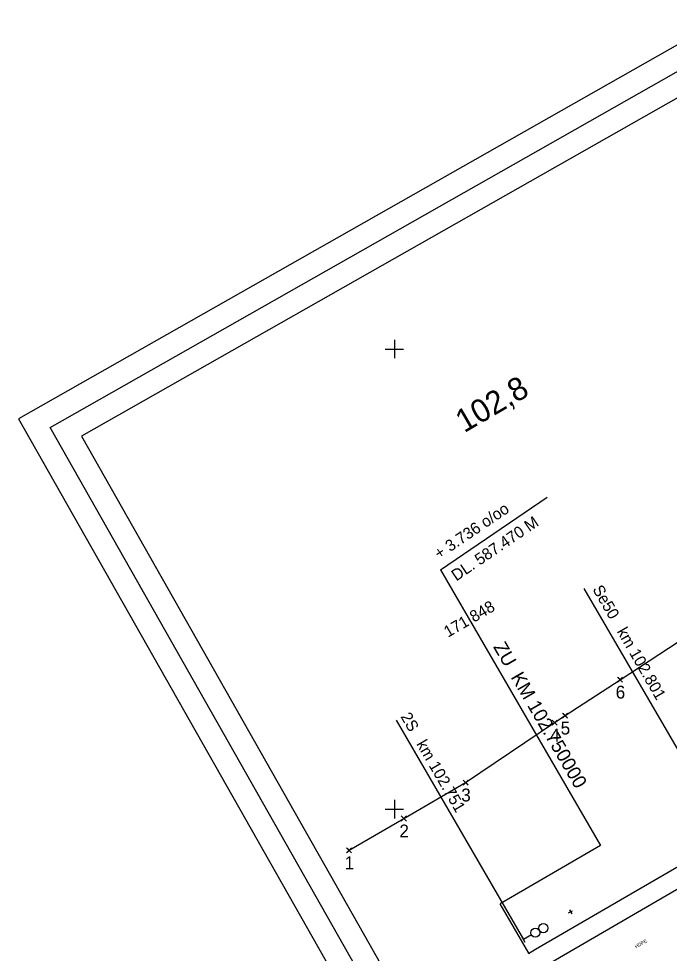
# Model space of a CAD drawing. Extents: x -566182 to -565305, y -1203073 to -1202401.
# Drawn here: x -566181.7 to -566040.2, y -1202931.3 to -1202728.2 of the extents above; entities that cross this region are included whole.
import ezdxf

# ---------------------------------------------------------------- set-up
doc = ezdxf.new("R2010")
doc.units = 0
for name, color, linetype in [('SZDC', 7, 'Continuous'), ('Vrstva 1', 7, 'Continuous'), ('Vrstva 12', 7, 'Continuous'), ('Vrstva 24', 7, 'Continuous'), ('Vrstva 25', 7, 'Continuous'), ('Vrstva 39', 7, 'Continuous'), ('Vrstva 42', 7, 'Continuous'), ('Vrstva 5', 7, 'Continuous'), ('Vrstva 6', 7, 'Continuous'), ('Vrstva 60', 7, 'Continuous'), ('Vrstva 7', 7, 'Continuous')]:
    doc.layers.add(name, color=color, linetype=linetype)

# ---------------------------------------------------------------- blocks, each defined once
blk = doc.blocks.new('C691')
at = {"layer": 'Vrstva 12'}
for p, q in [((-5, 0), (5, 0)), ((0, 5), (0, -5))]:
    blk.add_line(p, q, dxfattribs=at)
blk = doc.blocks.new('C569')
at = {"layer": 'Vrstva 24'}
for p, q in [((0, -7.5), (0, 7.5)), ((20, 0), (0, 0))]:
    blk.add_line(p, q, dxfattribs=at)
for centre in [(30, 0), (50, 0)]:
    blk.add_circle(centre, 10, dxfattribs=at)

msp = doc.modelspace()

# ---------------------------------------------------------------- linework, layer by layer
at = {"layer": 'SZDC'}
msp.add_lwpolyline([(-566109.86, -1202908.94), (-566097.96, -1202902.03), (-566084.51, -1202894.21), (-566065.16, -1202881.19), (-566062.89, -1202879.66), (-566050.93, -1202871.86), (-566034.12, -1202860.89), (-566014.69, -1202848.22), (-565999.33, -1202838.2), (-565981.56, -1202826.61), (-565964.56, -1202815.52), (-565946.25, -1202803.07), (-565943.74, -1202801.57), (-565935.57, -1202796.69), (-565927.13, -1202791.65), (-565924.54, -1202790.1), (-565905.03, -1202778.89), (-565894.6, -1202771.96), (-565883.49, -1202764.57), (-565860.68, -1202749.5), (-565834.73, -1202732.72)], dxfattribs=at)
at = {"layer": 'Vrstva 1'}
for points in [[(-566035.16, -1203073.47), (-565304.55, -1202658.99), (-565451.1, -1202400.68), (-566181.71, -1202815.16)], [(-565311.37, -1202657.11), (-566033.28, -1203066.66), (-566174.89, -1202817.04), (-565452.98, -1202407.49)], [(-566031.4, -1203059.85), (-565496.48, -1202756.39), (-565633.16, -1202515.46), (-566168.08, -1202818.92)]]:
    msp.add_lwpolyline(points, close=True, dxfattribs=at)
at = {"layer": 'Vrstva 5'}
for p, q in [((-566100, -1202798), (-566100, -1202802)), ((-566102, -1202800), (-566098, -1202800)), ((-566100, -1202898), (-566100, -1202902)), ((-566102, -1202900), (-566098, -1202900))]:
    msp.add_line(p, q, dxfattribs=at)
at = {"layer": 'Vrstva 6'}
for points in [[(-566068.74, -1202934.92), (-566067.2, -1202934.01), (-566009.26, -1202900.35), (-565952.55, -1202867.42), (-565900.78, -1202837.32), (-565844.77, -1202804.78), (-565792.03, -1202774.14)], [(-565967.23, -1202871.18), (-566010.28, -1202896.21), (-566069.32, -1202930.5), (-566070.86, -1202931.4)]]:
    msp.add_lwpolyline(points, dxfattribs=at)
at = {"layer": 'Vrstva 60'}
for p, q in [((-566090.01, -1202847.96), (-566066.79, -1202832.23)), ((-566090.01, -1202847.96), (-566055.2, -1202907.89)), ((-566058.78, -1202852.05), (-566029.01, -1202903.3)), ((-566050.48, -1202872.31), (-566051.48, -1202871.31)), ((-566050.48, -1202871.41), (-566051.48, -1202872.41)), ((-566051.38, -1202872.31), (-566050.38, -1202871.31)), ((-566051.38, -1202871.41), (-566050.38, -1202872.41)), ((-566050.93, -1202871.86), (-566050.93, -1202871.86)), ((-566062.44, -1202880.11), (-566063.44, -1202879.11)), ((-566062.44, -1202879.21), (-566063.44, -1202880.21)), ((-566063.34, -1202880.11), (-566062.34, -1202879.11)), ((-566063.34, -1202879.21), (-566062.34, -1202880.21)), ((-566099.63, -1202880.68), (-566071.96, -1202928.32)), ((-566064.71, -1202881.64), (-566065.71, -1202880.64)), ((-566064.71, -1202880.74), (-566065.71, -1202881.74)), ((-566065.61, -1202881.64), (-566064.61, -1202880.64)), ((-566065.61, -1202880.74), (-566064.61, -1202881.74)), ((-566065.16, -1202881.19), (-566065.16, -1202881.19)), ((-566062.89, -1202879.66), (-566062.89, -1202879.66)), ((-566084.06, -1202894.66), (-566085.06, -1202893.66)), ((-566084.06, -1202893.76), (-566085.06, -1202894.76)), ((-566084.96, -1202894.66), (-566083.96, -1202893.66)), ((-566084.96, -1202893.76), (-566083.96, -1202894.76)), ((-566084.51, -1202894.21), (-566084.51, -1202894.21)), ((-566097.51, -1202902.48), (-566098.51, -1202901.48)), ((-566097.51, -1202901.58), (-566098.51, -1202902.58)), ((-566098.41, -1202902.48), (-566097.41, -1202901.48)), ((-566098.41, -1202901.58), (-566097.41, -1202902.58)), ((-566097.96, -1202902.03), (-566097.96, -1202902.03)), ((-566055.2, -1202907.89), (-566077, -1202920.55)), ((-566109.41, -1202909.39), (-566110.41, -1202908.39)), ((-566109.41, -1202908.49), (-566110.41, -1202909.49)), ((-566110.31, -1202909.39), (-566109.31, -1202908.39)), ((-566110.31, -1202908.49), (-566109.31, -1202909.49)), ((-566109.86, -1202908.94), (-566109.86, -1202908.94)), ((-566070.75, -1202931.32), (-566077, -1202920.55))]:
    msp.add_line(p, q, dxfattribs=at)

# ---------------------------------------------------------------- block references
at = {"layer": 'Vrstva 12', "xscale": 0.09999990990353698, "yscale": 0.09999990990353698, "rotation": 30.000029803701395}
msp.add_blockref('C691', (-566061.7, -1202922.31), dxfattribs=at)
at = {"layer": 'Vrstva 24', "xscale": 0.10000006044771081, "yscale": 0.10000006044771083, "rotation": 29.642325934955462}
msp.add_blockref('C569', (-566071.96, -1202928.32), dxfattribs=at)

# ---------------------------------------------------------------- texts
at = {"layer": 'Vrstva 25'}
for s, p in [('Se50   km 102.801', (-566057.01, -1202852.19)), ('2S   km 102.751', (-566098.74, -1202879.86))]:
    msp.add_text(s, height=2.5, rotation=299.9873, dxfattribs=at).set_placement(p)
at = {"layer": 'Vrstva 39'}
for s, height, rotation, p in [('+ 3.736 o/oo', 2.5, 34.111, (-566090.27, -1202845.78)), ('DL. 587.470 M', 2.5, 34.111, (-566086.54, -1202850.53)), ('171.848', 2.5, 30.153, (-566088.35, -1202862.75)), ('ZU  KM 102.750000', 3, 300.153, (-566078.59, -1202864.73))]:
    msp.add_text(s, height=height, rotation=rotation, dxfattribs=at).set_placement(p)
at = {"layer": 'Vrstva 42'}
msp.add_text('HDPE', height=0.75, rotation=30.1468, dxfattribs=at).set_placement((-566047.46, -1202930.27))
at = {"layer": 'Vrstva 60'}
for s, p in [('6', (-566051.9, -1202875.97)), ('5', (-566063.86, -1202883.77)), ('4', (-566066.13, -1202885.3)), ('3', (-566085.48, -1202898.32)), ('2', (-566098.93, -1202906.14)), ('1', (-566110.83, -1202913.05))]:
    msp.add_text(s, height=2.8, dxfattribs=at).set_placement(p)
at = {"layer": 'Vrstva 7'}
msp.add_text('102,8', height=5, rotation=30.1698, dxfattribs=at).set_placement((-566084.83, -1202818.31))

doc.saveas('drawing.dxf')
